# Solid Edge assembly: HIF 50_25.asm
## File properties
Title: Zylinder
Author: ahadarics
Template: iso assembly.asm
Last saved by: ahadarics
Revision: 15
Application: Solid Edge
Username: ahadarics
Dokumentum tartalom típus: 1
Document Number: HIF 50/25
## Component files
Kit_2.par
Kit_1.par
Profilrohr 50_25.par
Kolbenstange 50_25.par
Mutter.par
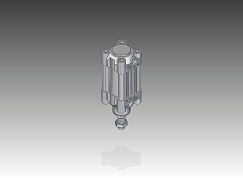
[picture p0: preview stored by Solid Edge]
